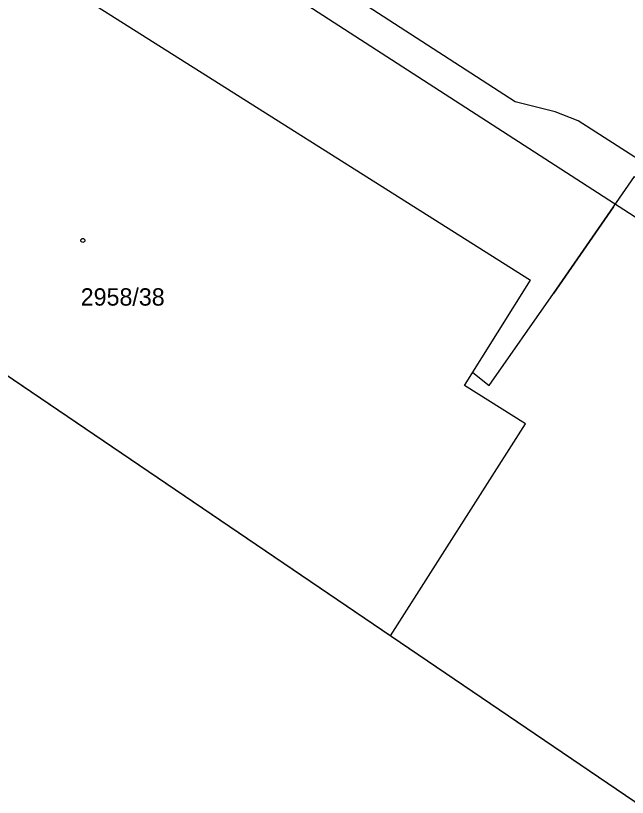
# Model space of a CAD drawing. Extents: x -621145 to -620023, y -1122866 to -1121971.
# Drawn here: x -620865.4 to -620812.6, y -1122442.6 to -1122375 of the extents above; entities that cross this region are included whole.
import ezdxf

# ---------------------------------------------------------------- set-up
doc = ezdxf.new("R2010")
doc.units = 0
for name, color, linetype in [('CETIN', 7, 'Continuous'), ('itself', 7, 'Continuous'), ('RÁMY', 7, 'Continuous'), ('Vrstva 55', 7, 'Continuous'), ('Vrstva 57', 7, 'Continuous')]:
    doc.layers.add(name, color=color, linetype=linetype)

msp = doc.modelspace()

# ---------------------------------------------------------------- linework, layer by layer
at = {"layer": 'CETIN'}
for points in [[(-620825.92, -1122405.87), (-620824.51, -1122406.99), (-620818.94, -1122399.06), (-620813.77, -1122391.56), (-620811.94, -1122388.94), (-620806.05, -1122392.88), (-620797.93, -1122398.39), (-620788.82, -1122404.57), (-620785.51, -1122405.86), (-620781.04, -1122408.44), (-620779.59, -1122408.85), (-620776.1, -1122410.97), (-620774.86, -1122411.81), (-620766.93, -1122416.76), (-620729.54, -1122440.11), (-620722.4, -1122445), (-620713.88, -1122450.37)], [(-620813.77, -1122391.56), (-620818.94, -1122399.06)]]:
    msp.add_lwpolyline(points, dxfattribs=at)
at = {"layer": 'itself'}
msp.add_lwpolyline([(-620721.666, -1122450.842), (-620745.766, -1122435.492), (-620776.456, -1122415.302), (-620776.396, -1122414.332), (-620775.686, -1122413.162), (-620774.756, -1122411.292), (-620776.986, -1122409.872), (-620778.946, -1122408.642), (-620781.216, -1122407.102), (-620786.306, -1122404.212), (-620792.996, -1122399.612), (-620794.806, -1122398.032), (-620806.306, -1122390.882), (-620816.806, -1122384.122), (-620818.796, -1122383.362), (-620822.246, -1122382.502), (-620843.096, -1122368.972), (-620871.286, -1122351.222), (-620896.976, -1122334.702), (-620917.616, -1122321.732), (-620932.526, -1122311.532), (-620939.766, -1122306.092)], dxfattribs=at)
at = {"layer": 'RÁMY'}
for points in [[(-621061.558, -1122093.918), (-620106.075, -1122742.822), (-620189.505, -1122865.67), (-621144.989, -1122216.766)], [(-620887.834, -1122211.901), (-620106.075, -1122742.822), (-620189.505, -1122865.67), (-620971.264, -1122334.748)]]:
    msp.add_lwpolyline(points, close=True, dxfattribs=at)
at = {"layer": 'Vrstva 55'}
for p, q in [((-620872.17, -1122365.51), (-620820.94, -1122397.9)), ((-620826.62, -1122407), (-620820.94, -1122397.9)), ((-620821.36, -1122410.31), (-620826.62, -1122407)), ((-620833.007, -1122428.644), (-620821.36, -1122410.31))]:
    msp.add_line(p, q, dxfattribs=at)
msp.add_lwpolyline([(-620804.955, -1122447.696), (-620781.81, -1122411.87), (-620848.87, -1122368.55)], dxfattribs=at)
at = {"layer": 'Vrstva 57'}
msp.add_circle((-620859.6, -1122394.47), 0.175, dxfattribs=at)

# ---------------------------------------------------------------- texts
msp.add_text('2958/38', height=1.5, dxfattribs=at).set_placement((-620859.779, -1122400.1))

doc.saveas('drawing.dxf')
